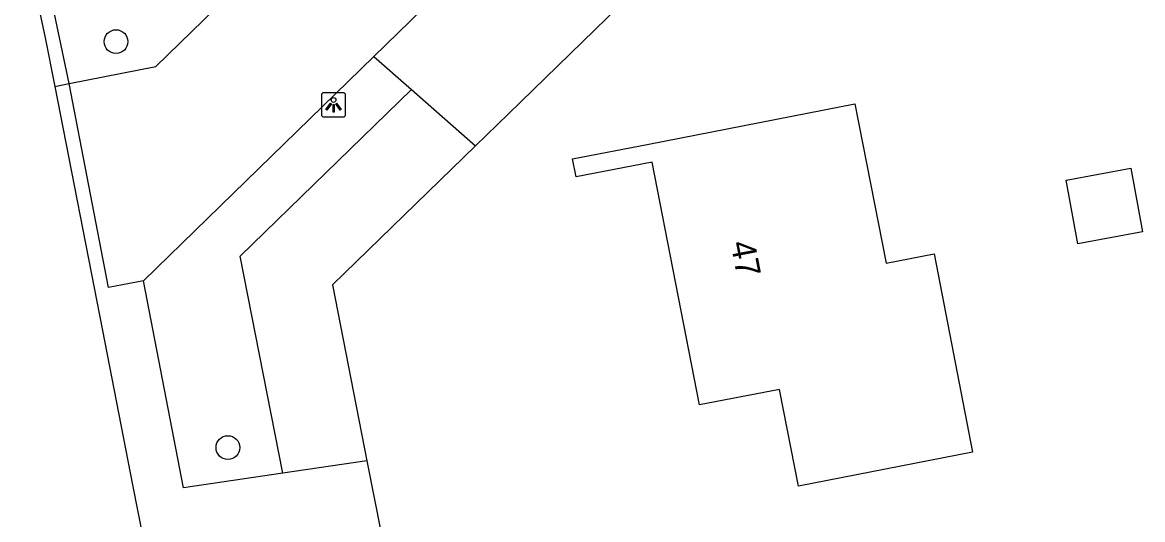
# Model space of a CAD drawing. Extents: x 157663 to 158496, y 379212 to 380934.
# Drawn here: x 158134.11 to 158180.23, y 380327.77 to 380348.23 of the extents above; entities that cross this region are included whole.
import ezdxf

# ---------------------------------------------------------------- set-up
doc = ezdxf.new("R2010")
doc.units = 0
for name, color, linetype in [('IMGEO_Boom', 7, 'Continuous'), ('IMGEO_Groenvoorziening', 7, 'Continuous'), ('IMGEO_Lichtpunt', 7, 'Continuous'), ('IMGEO_Pand', 7, 'Continuous'), ('IMGEO_Pand_nummerreeks', 7, 'Continuous'), ('IMGEO_Rijbaan_lokaal_open', 7, 'Continuous'), ('IMGEO_Voetpad_open', 7, 'Continuous')]:
    doc.layers.add(name, color=color, linetype=linetype)

msp = doc.modelspace()

# ---------------------------------------------------------------- linework, layer by layer
at = {"layer": 'IMGEO_Boom'}
for centre in [(158137.964, 380347.438), (158142.57, 380330.73)]:
    msp.add_circle(centre, 0.489, dxfattribs=at)
at = {"layer": 'IMGEO_Groenvoorziening'}
for points in [[(158177.909, 380367.608), (158154.125, 380344.473), (158152.771, 380343.156)], [(158148.577, 380346.821), (158150.127, 380345.467)], [(158144.831, 380329.673), (158143.082, 380338.615), (158150.127, 380345.467)], [(158150.127, 380345.467), (158152.771, 380343.156)], [(158152.771, 380343.156), (158146.881, 380337.427), (158148.297, 380330.186)]]:
    msp.add_lwpolyline(points, dxfattribs=at)
at = {"layer": 'IMGEO_Lichtpunt'}
for p, q in [((158146.422, 380345.24), (158146.422, 380344.433)), ((158146.422, 380345.24), (158146.422, 380344.433)), ((158147.324, 380345.335), (158146.516, 380345.335)), ((158147.324, 380345.335), (158146.516, 380345.335)), ((158147.418, 380344.433), (158147.418, 380345.24)), ((158147.418, 380344.433), (158147.418, 380345.24)), ((158146.516, 380344.339), (158147.324, 380344.339)), ((158146.516, 380344.339), (158147.324, 380344.339))]:
    msp.add_line(p, q, dxfattribs=at)
for points in [[(158146.796, 380344.904), (158146.835, 380344.876), (158146.647, 380344.614), (158146.609, 380344.641), (158146.796, 380344.904)], [(158146.898, 380344.856), (158146.945, 380344.856), (158146.945, 380344.534), (158146.898, 380344.534), (158146.898, 380344.856)], [(158147.008, 380344.876), (158147.046, 380344.903), (158147.233, 380344.641), (158147.194, 380344.613), (158147.008, 380344.876)]]:
    msp.add_lwpolyline(points, dxfattribs=at)
msp.add_circle((158146.921, 380345.038), 0.0994, dxfattribs=at)
for centre, start, end in [((158146.516, 380345.24), 90, 180), ((158146.516, 380345.24), 90, 180), ((158147.324, 380345.24), 0, 90), ((158147.324, 380345.24), 0, 90), ((158146.516, 380344.433), 180, 270), ((158146.516, 380344.433), 180, 270), ((158147.324, 380344.433), 270, 0), ((158147.324, 380344.433), 270, 360)]:
    msp.add_arc(centre, 0.0946, start, end, dxfattribs=at)
at = {"layer": 'IMGEO_Pand'}
for points in [[(158169.668, 380338.314), (158171.642, 380338.699), (158173.232, 380330.54), (158166.058, 380329.141), (158165.281, 380333.127), (158161.992, 380332.486), (158160.043, 380342.484), (158156.905, 380341.872), (158156.76, 380342.612), (158159.899, 380343.224), (158168.388, 380344.879), (158169.668, 380338.314)], [(158180.23, 380339.612), (158177.565, 380339.121), (158177.082, 380341.743), (158179.747, 380342.234), (158180.23, 380339.612)]]:
    msp.add_lwpolyline(points, dxfattribs=at)
at = {"layer": 'IMGEO_Rijbaan_lokaal_open'}
for points in [[(158173.119, 380370.694), (158148.577, 380346.821)], [(158136.036, 380345.72), (158139.607, 380346.417), (158147.967, 380354.554)], [(158134.11, 380351.967), (158135.053, 380347.592), (158135.443, 380345.596)], [(158139.093, 380337.595), (158148.577, 380346.821)], [(158139.093, 380337.595), (158137.661, 380337.318), (158136.036, 380345.72)], [(158135.443, 380345.596), (158137.406, 380335.543), (158138.646, 380329.194), (158139.517, 380324.752), (158142.973, 380307.119)]]:
    msp.add_lwpolyline(points, dxfattribs=at)
at = {"layer": 'IMGEO_Voetpad_open'}
for points in [[(158136.036, 380345.72), (158134.594, 380352.573)], [(158135.443, 380345.596), (158136.036, 380345.72)], [(158144.831, 380329.673), (158140.742, 380329.068), (158139.093, 380337.595)], [(158148.297, 380330.186), (158144.831, 380329.673)], [(158148.297, 380330.186), (158148.878, 380327.214)]]:
    msp.add_lwpolyline(points, dxfattribs=at)

# ---------------------------------------------------------------- texts
at = {"layer": 'IMGEO_Pand_nummerreeks'}
msp.add_text('47', height=1, rotation=281.0292, dxfattribs=at).set_placement((158163.261, 380339.148))

doc.saveas('drawing.dxf')
